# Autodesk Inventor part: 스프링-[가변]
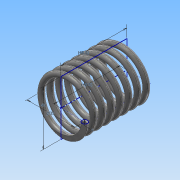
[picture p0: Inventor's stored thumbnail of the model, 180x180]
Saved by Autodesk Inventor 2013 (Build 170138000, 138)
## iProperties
Created: 2014-12
Part Number: 스프링-[가변]
Material: 강철, 탄소
Document SubType Name: Modeling
Designer: Administrator
Density: 7.87 g/cm^3
Mass: 80.2423 g
Surface Area: 103.211 cm^2
Volume: 10.196 cm^3
Author: Administrator
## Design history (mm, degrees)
sketch "스케치1"
  geometry: L1 (0, 0)-(0, 48.5); L2 (0, 0)-(17.5, 0); L3 (0, 48.5)-(17.5, 48.5); C1 r 2 at (17.5, 0)
  constraints: 6 end point, 1 centre point, 1 horizontal alignment, 1 parallel, 1 perpendicular, 1 vertical
  dimensions: "d0" = 48.5 distance of L1.start L1.end (derived); "d1" = 4 diameter of C1; "d2" = 35 diameter of L2.end L1
feature "코일1" sketch "스케치1" pitch "d3" = 10; turns "d5" = 7.5; dims "d4" = 48.5 (= d0), "d6" = 0, angle "d7" = 90 deg, angle "d8" = 90 deg, "d9" = 0, "d10" = 0
sketch "스케치2"
  geometry: L1 (48.5, -20)-(0, -20); L2 (0, -20)-(0, 20); L3 (0, 20)-(48.5, 20); L4 (48.5, 20)-(48.5, -20); 2 further points
  constraints: 8 end point, 2 parallel, 1 coincident, 1 horizontal, 1 midpoint, 1 perpendicular
  dimensions: "d11" = 48.5 distance of L2.end L3.end (derived); "d13" = 40 distance of L1.end L2.end
extrude "돌출1" sketch "스케치2" stored distance "d14" = 10; taper "d15" = 0 deg
node "솔리드1"
